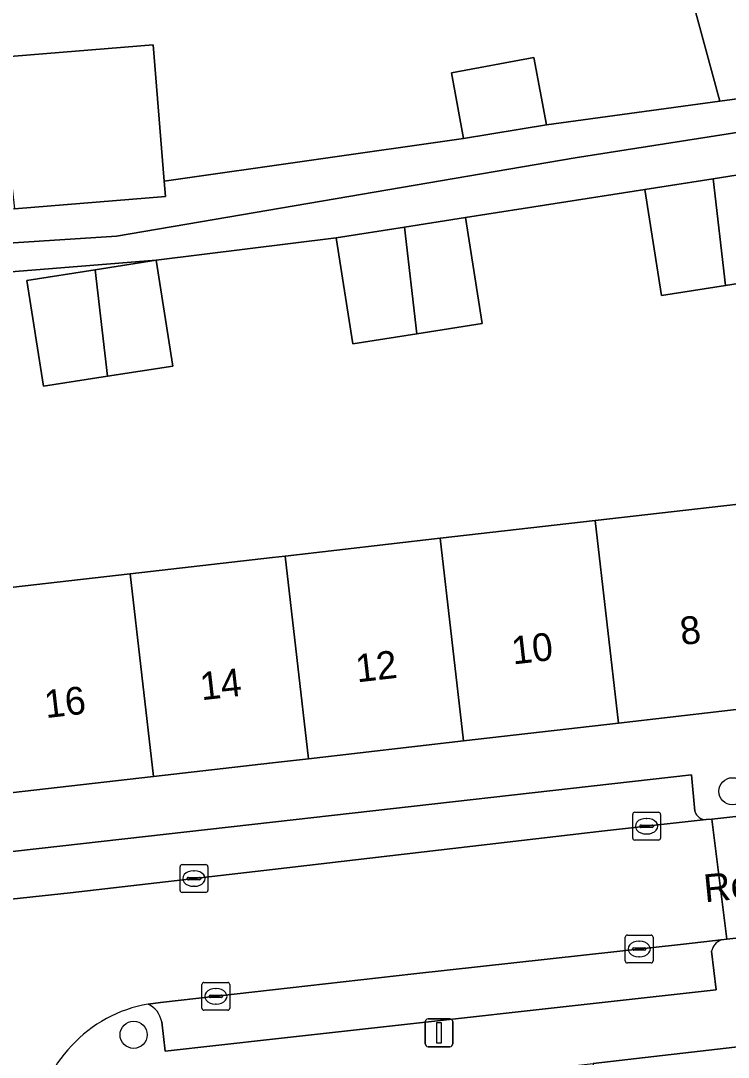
# Model space of a CAD drawing. Extents: x 162250 to 162661, y 380743 to 381606.
# Drawn here: x 162490.95 to 162516.38, y 380893.67 to 380930.93 of the extents above; entities that cross this region are included whole.
import ezdxf

# ---------------------------------------------------------------- set-up
doc = ezdxf.new("R2010")
doc.units = 0
for name, color, linetype in [('IMGEO_Boom', 7, 'Continuous'), ('IMGEO_Erf', 7, 'Continuous'), ('IMGEO_Kolk', 7, 'Continuous'), ('IMGEO_Lichtmast', 7, 'Continuous'), ('IMGEO_Openbare_ruimte_label', 7, 'Continuous'), ('IMGEO_Pand', 7, 'Continuous'), ('IMGEO_Pand_nummerreeks', 7, 'Continuous'), ('IMGEO_Parkeervlak_open', 7, 'Continuous'), ('IMGEO_Rijbaan_lokaal_open', 7, 'Continuous'), ('IMGEO_Voetpad_open', 7, 'Continuous')]:
    doc.layers.add(name, color=color, linetype=linetype)

msp = doc.modelspace()

# ---------------------------------------------------------------- linework, layer by layer
at = {"layer": 'IMGEO_Boom'}
for centre in [(162516.526, 380903.229), (162495.006, 380894.478)]:
    msp.add_circle(centre, 0.489, dxfattribs=at)
at = {"layer": 'IMGEO_Erf'}
for points in [[(162484.266, 380931.517), (162484.703, 380927.19), (162485.055, 380923.703), (162486.266, 380923.802), (162485.966, 380926.783), (162490.392, 380927.134), (162490.336, 380927.636), (162490.116, 380929.606), (162495.704, 380930.062), (162496.104, 380925.164), (162506.866, 380926.698), (162506.427, 380929.05), (162509.396, 380929.603), (162509.846, 380927.191), (162516.071, 380928.041), (162515.022, 380931.931)], [(162518.621, 380921.783), (162516.276, 380921.415), (162513.978, 380921.054), (162513.38, 380924.857), (162506.931, 380923.849), (162507.529, 380920.046), (162505.183, 380919.678), (162502.886, 380919.317), (162502.288, 380923.12), (162495.814, 380922.319), (162484.626, 380921.418)], [(162489.309, 380910.407), (162494.882, 380911.045), (162500, 380911.632), (162500.454, 380911.684), (162506.027, 380912.323), (162511.599, 380912.962), (162517.173, 380913.601)]]:
    msp.add_lwpolyline(points, dxfattribs=at)
msp.add_lwpolyline([(162495.814, 380922.319), (162496.412, 380918.516), (162494.067, 380918.148), (162491.769, 380917.787), (162491.171, 380921.59), (162493.627, 380921.976)], close=True, dxfattribs=at)
at = {"layer": 'IMGEO_Kolk'}
for p, q in [((162512.944, 380901.548), (162512.944, 380902.4)), ((162513.019, 380902.474), (162513.871, 380902.474)), ((162513.432, 380902.254), (162513.457, 380902.254)), ((162513.945, 380902.4), (162513.945, 380901.548)), ((162513.203, 380901.968), (162513.203, 380901.98)), ((162513.641, 380901.931), (162513.243, 380901.931)), ((162513.246, 380902.017), (162513.644, 380902.017)), ((162513.687, 380901.98), (162513.687, 380901.968)), ((162513.455, 380901.694), (162513.43, 380901.694)), ((162513.871, 380901.474), (162513.019, 380901.474)), ((162496.674, 380899.667), (162496.674, 380900.519)), ((162496.749, 380900.593), (162497.601, 380900.593)), ((162497.162, 380900.373), (162497.187, 380900.373)), ((162497.675, 380900.519), (162497.675, 380899.667)), ((162496.933, 380900.087), (162496.933, 380900.099)), ((162497.371, 380900.05), (162496.973, 380900.05)), ((162496.976, 380900.136), (162497.374, 380900.136)), ((162497.417, 380900.099), (162497.417, 380900.087)), ((162497.185, 380899.813), (162497.16, 380899.813)), ((162497.601, 380899.593), (162496.749, 380899.593)), ((162512.677, 380897.133), (162512.677, 380897.985)), ((162512.752, 380898.059), (162513.604, 380898.059)), ((162513.165, 380897.839), (162513.19, 380897.839)), ((162513.678, 380897.985), (162513.678, 380897.133)), ((162512.936, 380897.553), (162512.936, 380897.565)), ((162513.374, 380897.516), (162512.976, 380897.516)), ((162512.979, 380897.602), (162513.377, 380897.602)), ((162513.42, 380897.565), (162513.42, 380897.553)), ((162513.604, 380897.059), (162512.752, 380897.059)), ((162513.188, 380897.279), (162513.163, 380897.279)), ((162497.46, 380895.432), (162497.46, 380896.284)), ((162497.535, 380896.358), (162498.387, 380896.358)), ((162498.461, 380896.284), (162498.461, 380895.432)), ((162497.762, 380895.901), (162498.16, 380895.901)), ((162497.948, 380896.138), (162497.973, 380896.138)), ((162497.719, 380895.852), (162497.719, 380895.864)), ((162498.157, 380895.815), (162497.759, 380895.815)), ((162497.971, 380895.578), (162497.946, 380895.578)), ((162498.203, 380895.864), (162498.203, 380895.852)), ((162498.387, 380895.358), (162497.535, 380895.358))]:
    msp.add_line(p, q, dxfattribs=at)
for points in [[(162512.944, 380901.548), (162512.944, 380902.4)], [(162513.019, 380902.474), (162513.871, 380902.474)], [(162513.945, 380902.4), (162513.945, 380901.548)], [(162513.871, 380901.474), (162513.019, 380901.474)], [(162496.674, 380899.667), (162496.674, 380900.519)], [(162496.749, 380900.593), (162497.601, 380900.593)], [(162497.675, 380900.519), (162497.675, 380899.667)], [(162497.601, 380899.593), (162496.749, 380899.593)], [(162512.677, 380897.133), (162512.677, 380897.985)], [(162512.752, 380898.059), (162513.604, 380898.059)], [(162513.678, 380897.985), (162513.678, 380897.133)], [(162513.604, 380897.059), (162512.752, 380897.059)], [(162497.46, 380895.432), (162497.46, 380896.284)], [(162497.535, 380896.358), (162498.387, 380896.358)], [(162498.461, 380896.284), (162498.461, 380895.432)], [(162498.387, 380895.358), (162497.535, 380895.358)]]:
    msp.add_lwpolyline(points, dxfattribs=at)
for centre, radius, start, end in [((162513.021, 380902.398), 0.0765, 91.552, 178.448), ((162513.021, 380902.398), 0.0765, 91.552, 178.448), ((162513.869, 380902.398), 0.0765, 1.552, 88.448), ((162513.869, 380902.398), 0.0765, 1.552, 88.448), ((162513.243, 380901.977), 0.0403, 85.8775, 175.7526), ((162513.24, 380901.967), 0.0366, 178.938, 274.7102), ((162513.644, 380901.974), 0.043, 264.8664, 352.4533), ((162513.648, 380901.979), 0.0386, 1.7309, 96.639), ((162513.021, 380901.55), 0.0765, 181.552, 268.448), ((162513.021, 380901.55), 0.0765, 181.552, 268.448), ((162513.869, 380901.55), 0.0765, 271.552, 358.448), ((162513.869, 380901.55), 0.0765, 271.552, 358.448), ((162496.751, 380900.517), 0.0765, 91.552, 178.448), ((162496.751, 380900.517), 0.0765, 91.552, 178.448), ((162497.599, 380900.517), 0.0765, 1.552, 88.448), ((162497.599, 380900.517), 0.0765, 1.552, 88.448), ((162496.973, 380900.096), 0.0403, 85.8775, 175.7526), ((162496.97, 380900.086), 0.0366, 178.938, 274.7102), ((162497.374, 380900.093), 0.043, 264.8664, 352.4533), ((162497.378, 380900.098), 0.0386, 1.7309, 96.639), ((162496.751, 380899.669), 0.0765, 181.552, 268.448), ((162496.751, 380899.669), 0.0765, 181.552, 268.448), ((162497.599, 380899.669), 0.0765, 271.552, 358.448), ((162497.599, 380899.669), 0.0765, 271.552, 358.448), ((162512.754, 380897.983), 0.0765, 91.552, 178.448), ((162512.754, 380897.983), 0.0765, 91.552, 178.448), ((162513.602, 380897.983), 0.0765, 1.552, 88.448), ((162513.602, 380897.983), 0.0765, 1.552, 88.448), ((162512.976, 380897.562), 0.0403, 85.8775, 175.7526), ((162512.973, 380897.552), 0.0366, 178.938, 274.7102), ((162513.377, 380897.559), 0.043, 264.8664, 352.4533), ((162513.381, 380897.564), 0.0386, 1.7309, 96.639), ((162512.754, 380897.135), 0.0765, 181.552, 268.448), ((162512.754, 380897.135), 0.0765, 181.552, 268.448), ((162513.602, 380897.135), 0.0765, 271.552, 358.448), ((162513.602, 380897.135), 0.0765, 271.552, 358.448), ((162497.537, 380896.282), 0.0765, 91.552, 178.448), ((162497.537, 380896.282), 0.0765, 91.552, 178.448), ((162498.385, 380896.282), 0.0765, 1.552, 88.448), ((162498.385, 380896.282), 0.0765, 1.552, 88.448), ((162497.759, 380895.861), 0.0403, 85.8775, 175.7526), ((162498.164, 380895.863), 0.0386, 1.7309, 96.639), ((162497.756, 380895.851), 0.0366, 178.938, 274.7102), ((162498.16, 380895.858), 0.043, 264.8664, 352.4533), ((162497.537, 380895.434), 0.0765, 181.552, 268.448), ((162497.537, 380895.434), 0.0765, 181.552, 268.448), ((162498.385, 380895.434), 0.0765, 271.552, 358.448), ((162498.385, 380895.434), 0.0765, 271.552, 358.448)]:
    msp.add_arc(centre, radius, start, end, dxfattribs=at)
for centre, major_axis, ratio, start_param, end_param in [((162513.431, 380901.974), (-0.387, 0.002), 0.722429, 4.712389, 7.853982), ((162513.456, 380901.974), (-0.39, 0.002), 0.717154, 1.570796, 4.712389), ((162497.161, 380900.093), (-0.387, 0.002), 0.722429, 4.712389, 7.853982), ((162497.186, 380900.093), (-0.39, 0.002), 0.717154, 1.570796, 4.712389), ((162513.164, 380897.559), (-0.387, 0.002), 0.722429, 4.712389, 7.853982), ((162513.189, 380897.559), (-0.39, 0.002), 0.717154, 1.570796, 4.712389), ((162497.947, 380895.858), (-0.387, 0.002), 0.722429, 4.712389, 7.853982), ((162497.972, 380895.858), (-0.39, 0.002), 0.717154, 1.570796, 4.712389)]:
    msp.add_ellipse(centre, major_axis=major_axis, ratio=ratio, start_param=start_param, end_param=end_param, dxfattribs=at)
at = {"layer": 'IMGEO_Lichtmast'}
for p, q in [((162505.487, 380894.149), (162505.487, 380894.949)), ((162505.487, 380894.949), (162505.487, 380894.149)), ((162505.587, 380895.049), (162506.377, 380895.049)), ((162506.377, 380895.049), (162505.587, 380895.049)), ((162506.477, 380894.949), (162506.477, 380894.149)), ((162506.477, 380894.149), (162506.477, 380894.949)), ((162506.377, 380894.049), (162505.587, 380894.049)), ((162505.587, 380894.049), (162506.377, 380894.049))]:
    msp.add_line(p, q, dxfattribs=at)
msp.add_lwpolyline([(162505.907, 380894.924), (162506.057, 380894.924), (162506.057, 380894.174), (162505.907, 380894.174), (162505.907, 380894.924)], dxfattribs=at)
for centre, start, end in [((162505.587, 380894.949), 90, 180), ((162505.587, 380894.949), 90, 180), ((162506.377, 380894.949), 0, 90), ((162506.377, 380894.949), 360, 90), ((162505.587, 380894.149), 180, 270), ((162505.587, 380894.149), 180, 270), ((162506.377, 380894.149), 270, 0), ((162506.377, 380894.149), 270, 0)]:
    msp.add_arc(centre, 0.1, start, end, dxfattribs=at)
at = {"layer": 'IMGEO_Pand'}
for points in [[(162520.22, 380933.293), (162515.022, 380931.931), (162516.071, 380928.041), (162521.472, 380928.769), (162521.145, 380929.952)], [(162495.704, 380930.062), (162490.116, 380929.606), (162490.336, 380927.636), (162490.392, 380927.134), (162490.724, 380924.166), (162496.149, 380924.609), (162496.104, 380925.164)], [(162509.396, 380929.603), (162506.427, 380929.05), (162506.866, 380926.698), (162509.846, 380927.191)], [(162515.836, 380925.243), (162516.276, 380921.415), (162518.621, 380921.783), (162518.023, 380925.586)], [(162515.836, 380925.243), (162513.38, 380924.857), (162513.978, 380921.054), (162516.276, 380921.415)], [(162504.744, 380923.506), (162505.183, 380919.678), (162507.529, 380920.046), (162506.931, 380923.849)], [(162504.744, 380923.506), (162502.288, 380923.12), (162502.886, 380919.317), (162505.183, 380919.678)], [(162494.067, 380918.148), (162496.412, 380918.516), (162495.814, 380922.319), (162493.627, 380921.976)], [(162494.067, 380918.148), (162493.627, 380921.976), (162491.171, 380921.59), (162491.769, 380917.787)], [(162512.435, 380905.679), (162518.009, 380906.32), (162517.173, 380913.601), (162511.599, 380912.962)], [(162512.435, 380905.679), (162511.599, 380912.962), (162506.027, 380912.323), (162506.864, 380905.038)], [(162506.864, 380905.038), (162506.027, 380912.323), (162500.454, 380911.684), (162501.291, 380904.397)], [(162494.882, 380911.045), (162495.718, 380903.759), (162500, 380904.249), (162501.291, 380904.397), (162500.454, 380911.684), (162500, 380911.632)], [(162494.882, 380911.045), (162489.309, 380910.407), (162490.145, 380903.121), (162495.718, 380903.759)], [(162511.52, 380893.448), (162512.345, 380886.245), (162518.058, 380886.891), (162517.802, 380889.133), (162517.236, 380894.1)]]:
    msp.add_lwpolyline(points, close=True, dxfattribs=at)
at = {"layer": 'IMGEO_Parkeervlak_open'}
for points in [[(162515.182, 380902.51), (162515.054, 380903.819), (162500, 380902.119), (162479.285, 380899.779), (162479.401, 380898.674)], [(162511.929, 380901.805), (162515.59, 380902.21)], [(162479.093, 380898.117), (162492.727, 380899.574), (162500, 380900.419), (162511.929, 380901.805)], [(162516.124, 380897.889), (162514.767, 380897.736), (162505.08, 380896.666), (162500, 380896.091), (162495.975, 380895.635), (162495.523, 380895.578)], [(162496.014, 380894.943), (162496.137, 380893.889), (162500, 380894.319), (162515.941, 380896.095), (162515.782, 380897.48)]]:
    msp.add_lwpolyline(points, dxfattribs=at)
for centre, radius, start, end in [((162515.573, 380902.614), 0.404, 194.9077, 272.4386), ((162516.338, 380897.362), 0.568, 112.1293, 168.0669), ((162495.165, 380894.794), 0.862, 9.9698, 65.4546)]:
    msp.add_arc(centre, radius, start, end, dxfattribs=at)
at = {"layer": 'IMGEO_Rijbaan_lokaal_open'}
msp.add_lwpolyline([(162495.523, 380895.578), (162495.975, 380895.635), (162500, 380896.091), (162505.08, 380896.666), (162514.767, 380897.736), (162516.124, 380897.889), (162516.326, 380897.912), (162515.784, 380902.231), (162515.59, 380902.21), (162511.929, 380901.805), (162500, 380900.419), (162492.727, 380899.574), (162479.093, 380898.117), (162475.588, 380895.901), (162475.389, 380895.823), (162451.796, 380895.213), (162449.487, 380895.131), (162437.959, 380894.918), (162437.76, 380894.915), (162437.985, 380890.004), (162438.016, 380890.02)], dxfattribs=at)
msp.add_lwpolyline([(162516.326, 380897.912), (162519.345, 380898.253), (162518.93, 380902.579), (162515.784, 380902.231)], close=True, dxfattribs=at)
for centre, radius, start, end in [((162496.352, 380890.771), 4.878, 99.7885, 137.2073), ((162495.589, 380891.321), 3.946, 135.5373, 181.6448)]:
    msp.add_arc(centre, radius, start, end, dxfattribs=at)
at = {"layer": 'IMGEO_Voetpad_open'}
msp.add_lwpolyline([(162510.88, 380925.996), (162534.644, 380929.722), (162534.346, 380931.232), (162526.8, 380929.72), (162521.472, 380928.769), (162516.071, 380928.041), (162509.846, 380927.191), (162506.866, 380926.698), (162496.104, 380925.164), (162496.149, 380924.609), (162490.724, 380924.166), (162486.266, 380923.802), (162485.055, 380923.703), (162476.958, 380923.043), (162467.301, 380922.256), (162467.389, 380921.174), (162482.883, 380922.444), (162494.393, 380923.178), (162498.395, 380923.862)], close=True, dxfattribs=at)
for points in [[(162534.644, 380929.722), (162510.88, 380925.996), (162498.395, 380923.862), (162494.393, 380923.178), (162482.883, 380922.444), (162467.389, 380921.174)], [(162474.973, 380901.608), (162478.879, 380901.832), (162478.308, 380906.8), (162478.033, 380909.114), (162476.509, 380908.939), (162476.189, 380912.242), (162476.043, 380920.727), (162480.255, 380921.062), (162482.42, 380921.238), (162484.626, 380921.418), (162495.814, 380922.319), (162502.288, 380923.12), (162504.744, 380923.506), (162506.931, 380923.849), (162513.38, 380924.857), (162515.836, 380925.243), (162518.023, 380925.586)], [(162539.077, 380904.911), (162538.167, 380911.895), (162534.512, 380911.16), (162534.846, 380908.256), (162529.153, 380907.601), (162523.581, 380906.961), (162518.009, 380906.32), (162512.435, 380905.679), (162506.864, 380905.038), (162501.291, 380904.397), (162500, 380904.249), (162495.718, 380903.759), (162490.145, 380903.121), (162484.572, 380902.483), (162478.879, 380901.832), (162474.973, 380901.608), (162469.232, 380901.403), (162463.61, 380901.203), (162457.987, 380901.002), (162452.364, 380900.801), (162446.741, 380900.601), (162441.119, 380900.4)], [(162500, 380902.119), (162515.054, 380903.819), (162515.182, 380902.51)], [(162515.59, 380902.21), (162515.784, 380902.231), (162518.93, 380902.579), (162519.094, 380902.597)], [(162479.401, 380898.674), (162479.285, 380899.779), (162500, 380902.119)], [(162519.345, 380898.253), (162516.326, 380897.912), (162516.124, 380897.889)], [(162515.782, 380897.48), (162515.941, 380896.095), (162500, 380894.319), (162496.137, 380893.889), (162496.014, 380894.943)], [(162491.645, 380891.208), (162491.648, 380891.122), (162493.634, 380891.39), (162494.616, 380891.523), (162500, 380892.136), (162500.33, 380892.174), (162505.925, 380892.811), (162511.52, 380893.448), (162517.236, 380894.1), (162520.08, 380894.444), (162532.211, 380895.911), (162532.466, 380894.986), (162539.411, 380896.403)]]:
    msp.add_lwpolyline(points, dxfattribs=at)
for centre, radius, start, end in [((162515.573, 380902.614), 0.404, 194.9077, 272.4386), ((162516.338, 380897.362), 0.568, 112.1293, 168.0669), ((162496.352, 380890.771), 4.878, 99.7885, 137.2073), ((162495.165, 380894.794), 0.862, 9.9698, 65.4546), ((162495.589, 380891.321), 3.946, 135.5373, 181.6448)]:
    msp.add_arc(centre, radius, start, end, dxfattribs=at)

# ---------------------------------------------------------------- texts
at = {"layer": 'IMGEO_Openbare_ruimte_label'}
msp.add_text('Resedastraat', height=1, rotation=5.568, dxfattribs=at).set_placement((162515.544, 380899.236))
at = {"layer": 'IMGEO_Pand_nummerreeks'}
for s, p in [('8', (162514.701, 380908.481)), ('10', (162508.645, 380907.785)), ('12', (162503.042, 380907.142)), ('14', (162497.449, 380906.499)), ('16', (162491.852, 380905.857))]:
    msp.add_text(s, height=1, rotation=6.5479, dxfattribs=at).set_placement(p)

doc.saveas('drawing.dxf')
